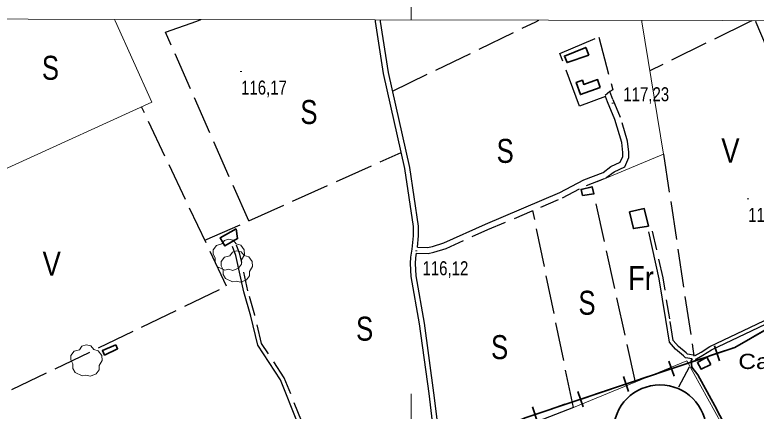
# Model space of a CAD drawing. Extents: x 483840 to 488445, y 4386047 to 4389027.
# Drawn here: x 484752.4 to 485215.3, y 4388514.2 to 4388761.9 of the extents above; entities that cross this region are included whole.
import ezdxf
from ezdxf.enums import TextEntityAlignment as Align

# ---------------------------------------------------------------- set-up
doc = ezdxf.new("R2010")
doc.units = 0
doc.header["$LTSCALE"] = 4
doc.linetypes.add('LONG_DASHED', pattern=[7.5, 6, -1.5])
doc.linetypes.add('MEDIUM_DASHED', pattern=[4.5, 3, -1.5])
for name, color, linetype, lineweight in [('1', 7, 'Continuous', 13), ('25', 7, 'LONG_DASHED', 25), ('29', 7, 'Continuous', 13), ('34', 7, 'Continuous', 35), ('38', 7, 'Continuous', 25), ('47', 7, 'Continuous', 35), ('51', 7, 'Continuous', 13), ('6', 7, 'Continuous', 35), ('7', 7, 'Continuous', 13)]:
    doc.layers.add(name, color=color, linetype=linetype, lineweight=lineweight)
doc.layers.add('31', color=7, linetype='Continuous')
doc.layers.add('5', color=7, linetype='Continuous')

msp = doc.modelspace()

# ---------------------------------------------------------------- linework, layer by layer
at = {"layer": '1'}
for p, q in [((485000, 4388758.61), (485000, 4388830.03)), ((485000, 4388525), (485000, 4388475))]:
    msp.add_line(p, q, dxfattribs=at)
msp.add_lwpolyline([(484110.5, 4388760.3), (487685.8, 4388753.5), (487681.9, 4386441.2), (484105.5, 4386448.1)], close=True, dxfattribs=at)
at = {"layer": '25'}
for p, q in [((484866.02, 4388757.98), (484868.47, 4388758.86)), ((484988.3, 4388714.2), (485077.74, 4388757.57)), ((485077.74, 4388757.57), (485079.57, 4388758.46)), ((485210.85, 4388757.32), (485149, 4388726.92)), ((485212.66, 4388758.2), (485210.85, 4388757.31)), ((485214.84, 4388758.2), (485215.21, 4388757.31)), ((485157.51, 4388674.83), (485176.51, 4388548.51)), ((485139.96, 4388532.34), (485113.97, 4388649.93)), ((485101.21, 4388516.39), (485075.87, 4388639.56)), ((485101.21, 4388516.39), (485020.66, 4388485.07))]:
    msp.add_line(p, q, dxfattribs=at)
for points in [[(484898.44, 4388633.15), (484846.53, 4388750.99), (484866.02, 4388757.98)], [(485215.21, 4388757.31), (485234.26, 4388712.09), (485248.14, 4388586.71)], [(485121.21, 4388710.73), (485105.1, 4388704.83), (485092.82, 4388737.67), (485117.03, 4388747.98), (485125.86, 4388714.91), (485123.99, 4388713.95), (485120.96, 4388711.39)], [(484723.49, 4388514.66), (484884.67, 4388592.25), (484831.6, 4388704.3)], [(484871.02, 4388621.09), (484898.5, 4388633.03), (484993.75, 4388675.81)]]:
    msp.add_lwpolyline(points, dxfattribs=at)
at = {"layer": '29'}
for points in [[(484883.46, 4388602.26), (484878.92, 4388604.38), (484877.51, 4388606.92), (484877.61, 4388609.9), (484876.24, 4388612.31), (484876.28, 4388615.06), (484878.44, 4388617.66), (484881.63, 4388618.66), (484883.28, 4388620.85), (484885.85, 4388621.68), (484888.71, 4388621.03), (484890.66, 4388618.76), (484893.47, 4388617.94), (484895.6, 4388615.09), (484895.84, 4388611.96), (484893.96, 4388608.81), (484893.96, 4388606.13), (484892.14, 4388603.52), (484888.52, 4388602.18), (484885.75, 4388602.81)], [(484888.43, 4388594.92), (484883.89, 4388597.04), (484882.48, 4388599.58), (484882.58, 4388602.56), (484881.21, 4388604.97), (484881.25, 4388607.72), (484883.41, 4388610.32), (484886.6, 4388611.32), (484888.25, 4388613.51), (484890.82, 4388614.34), (484893.68, 4388613.69), (484895.63, 4388611.42), (484898.44, 4388610.6), (484900.57, 4388607.75), (484900.81, 4388604.62), (484898.93, 4388601.47), (484898.93, 4388598.79), (484897.11, 4388596.18), (484893.49, 4388594.84), (484890.72, 4388595.47)], [(484794.53, 4388536.18), (484789.99, 4388538.3), (484788.58, 4388540.84), (484788.68, 4388543.82), (484787.31, 4388546.23), (484787.35, 4388548.98), (484789.51, 4388551.58), (484792.7, 4388552.58), (484794.35, 4388554.77), (484796.92, 4388555.6), (484799.78, 4388554.95), (484801.73, 4388552.68), (484804.54, 4388551.86), (484806.67, 4388549.01), (484806.91, 4388545.88), (484805.03, 4388542.73), (484805.03, 4388540.05), (484803.21, 4388537.44), (484799.59, 4388536.1), (484796.82, 4388536.73)]]:
    msp.add_lwpolyline(points, close=True, dxfattribs=at)
at = {"layer": '34'}
for p, q in [((485213.53, 4388560.61), (485222.2, 4388565.59)), ((485186.17, 4388548.68), (485195.65, 4388551.87)), ((485189.32, 4388555.02), (485192.5, 4388545.54)), ((485171.96, 4388543.91), (485181.44, 4388547.09)), ((485157.74, 4388539.13), (485167.22, 4388542.32)), ((485160.89, 4388545.47), (485164.07, 4388535.99)), ((485143.53, 4388534.36), (485153.01, 4388537.55)), ((485129.31, 4388529.59), (485138.79, 4388532.77)), ((485132.46, 4388535.92), (485135.64, 4388526.44)), ((485115.1, 4388524.81), (485124.58, 4388528)), ((485100.88, 4388520.04), (485110.36, 4388523.22)), ((485104.03, 4388526.37), (485107.21, 4388516.89)), ((485086.67, 4388515.26), (485096.15, 4388518.45)), ((485075.6, 4388516.82), (485078.79, 4388507.34))]:
    msp.add_line(p, q, dxfattribs=at)
for points in [[(484742, 4388368), (485071, 4388510), (485202, 4388554), (485338, 4388632), (485442, 4388724), (485439, 4388753), (485444.8, 4388757.76)], [(485200.39, 4388553.46), (485202, 4388554), (485209.2, 4388558.13)]]:
    msp.add_lwpolyline(points, dxfattribs=at)
at = {"layer": '38'}
for p, q in [((484977.67, 4388757.77), (484977.54, 4388758.65)), ((484980.82, 4388757.76), (484980.69, 4388758.64))]:
    msp.add_line(p, q, dxfattribs=at)
for points in [[(485015.38, 4388489.87), (485011.07, 4388525.18), (485005.15, 4388568.67), (485000, 4388598.29), (484999.53, 4388606.46), (484999.68, 4388610.36), (485000.57, 4388615.38), (485001.38, 4388623.79), (485001.37, 4388629.5), (484995.99, 4388665.8), (484982.61, 4388725.27), (484977.67, 4388757.77)], [(485003.81, 4388616.64), (485004.49, 4388623.64), (485004.48, 4388629.73), (484999.05, 4388666.37), (484985.67, 4388725.84), (484980.82, 4388757.76)], [(485177.32, 4388548.97), (485180.97, 4388551.04), (485186.43, 4388554.5), (485220.16, 4388570.53), (485259.22, 4388593.11), (485283.5, 4388609.42), (485318.8, 4388629.88), (485358.29, 4388660.64), (485386.3, 4388683.42), (485423.85, 4388710.78), (485435.76, 4388721.99), (485438.46, 4388724.47), (485441.33, 4388727.59)], [(485177.05, 4388545.26), (485178.07, 4388546.88), (485182.09, 4388549.16), (485187.49, 4388552.58), (485221.18, 4388568.6), (485260.38, 4388591.25), (485284.66, 4388607.57), (485320.02, 4388628.07), (485359.66, 4388658.93), (485387.64, 4388681.69), (485425.25, 4388709.1), (485437.25, 4388720.39), (485439.94, 4388722.85), (485442.73, 4388725.7)], [(485003.81, 4388616.64), (485010.2, 4388616.38), (485013.13, 4388617.06), (485020.33, 4388619.4), (485046.26, 4388631.07), (485092.81, 4388650.8), (485107.8, 4388658.7), (485119.72, 4388663.37), (485124.67, 4388666.98), (485130.51, 4388669.69), (485132.01, 4388673.37), (485132, 4388675.92), (485131.39, 4388682.14), (485127.1, 4388696.46), (485122.43, 4388707.48), (485121.2, 4388710.73)], [(485175.43, 4388546.79), (485171.3, 4388547.56), (485169.95, 4388548.76), (485165.06, 4388552.87), (485161.23, 4388557.22), (485158.88, 4388571.54), (485154.79, 4388596.97), (485148.21, 4388626.21)], [(484951.52, 4388457.57), (484949.39, 4388465.73), (484940.36, 4388482.97), (484928.92, 4388507.18), (484918.37, 4388533.79), (484904.08, 4388555.37), (484899.78, 4388573.59), (484895.33, 4388588.74), (484890.42, 4388611.54), (484888.38, 4388617.01)], [(485037.47, 4388447.58), (485024.35, 4388478.07), (485020.87, 4388484.49), (485018.37, 4388491.05), (485014.15, 4388525.57), (485008.22, 4388569.14), (485003.09, 4388598.65), (485002.64, 4388606.49), (485002.78, 4388610.02), (485003.29, 4388612.91)]]:
    msp.add_lwpolyline(points, dxfattribs=at)
at = {"layer": '38', "linetype": 'MEDIUM_DASHED'}
for points in [[(485003.29, 4388612.91), (485010.55, 4388612.62), (485014.13, 4388613.45), (485021.68, 4388615.9), (485047.76, 4388627.64), (485094.42, 4388647.42), (485109.36, 4388655.29), (485121.53, 4388660.06), (485126.58, 4388663.74), (485133.42, 4388666.91), (485135.76, 4388672.64), (485135.74, 4388676.11), (485135.08, 4388682.87), (485130.63, 4388697.73), (485125.9, 4388708.87), (485123.98, 4388713.94)], [(485177.32, 4388548.97), (485172.43, 4388549.87), (485171.57, 4388550.64), (485166.8, 4388554.65), (485163.56, 4388558.32), (485161.33, 4388571.94), (485157.23, 4388597.44), (485150.63, 4388626.76)], [(484953.97, 4388458.58), (484951.85, 4388466.67), (484942.7, 4388484.14), (484931.32, 4388508.22), (484920.7, 4388535.01), (484906.52, 4388556.43), (484902.31, 4388574.26), (484897.87, 4388589.38), (484892.94, 4388612.28), (484890.83, 4388617.92)]]:
    msp.add_lwpolyline(points, dxfattribs=at)
at = {"layer": '47'}
for points in [[(485110.9, 4388736.57), (485108.87, 4388741.52), (485095.64, 4388736.09), (485097.29, 4388732.04)], [(485117.99, 4388716.48), (485116.33, 4388721.35), (485107.68, 4388718.4), (485106.81, 4388720.93), (485103.04, 4388719.64), (485105.63, 4388712.03)], [(485113.97, 4388649.93), (485112.84, 4388654.43), (485106, 4388652.74), (485106.92, 4388649)], [(485148.06, 4388629.74), (485145.49, 4388640.76), (485136.27, 4388638.64), (485138.65, 4388628.27)], [(484890.61, 4388628.19), (484880.72, 4388622.55), (484883.6, 4388617.49), (484891.48, 4388621.98)], [(484815.42, 4388555.68), (484816.62, 4388553.13), (484808.42, 4388549.27), (484807.11, 4388552.03)], [(485187.13, 4388543.38), (485184.5, 4388547.95), (485178.6, 4388544.56), (485180.96, 4388540.44)]]:
    msp.add_lwpolyline(points, close=True, dxfattribs=at)
at = {"layer": '51'}
for p, q in [((484815.1, 4388758.08), (484814.7, 4388758.96)), ((485143.99, 4388757.44), (485143.84, 4388758.33))]:
    msp.add_line(p, q, dxfattribs=at)
for points in [[(484662.5, 4388627.22), (484838.05, 4388707.24), (484815.1, 4388758.08)], [(485116.06, 4388657.44), (485157.51, 4388674.83), (485143.99, 4388757.45)], [(485202.67, 4388490.22), (485172.05, 4388545.53), (485101.21, 4388516.39)]]:
    msp.add_lwpolyline(points, dxfattribs=at)
at = {"layer": '6', "lineweight": 25}
msp.add_line((485167.04, 4388529.47), (485173.78, 4388541.83), dxfattribs=at)
at = {"layer": '6'}
msp.add_lwpolyline([(485224.04, 4388447.11), (485207.78, 4388482.2), (485189.48, 4388517.58), (485178.95, 4388536.92), (485175.21, 4388541.77), (485174.76, 4388545.72), (485175.43, 4388546.79)], dxfattribs=at)
msp.add_circle((485155.26, 4388501.45), 29.1, dxfattribs=at)
at = {"layer": '7'}
for p, q in [((484893.18, 4388726.39), (484894.18, 4388726.39)), ((485125.15, 4388706.66), (485126.15, 4388706.66)), ((485209.79, 4388646.79), (485210.79, 4388646.79)), ((485002.58, 4388614.27), (485003.58, 4388614.27))]:
    msp.add_line(p, q, dxfattribs=at)

# ---------------------------------------------------------------- texts
at = {"layer": '31'}
for s, width, p in [('S', 0.8, (484774.65, 4388721.25)), ('S', 0.8, (484936.07, 4388693.6)), ('S', 0.8, (485058.61, 4388669.34)), ('V', 0.85, (485199.28, 4388669.57)), ('V', 0.85, (484775.45, 4388598.77)), ('Fr', 0.85, (485143.39, 4388589.8)), ('S', 0.8, (485109.7, 4388574.43)), ('S', 0.8, (484970.84, 4388558.21)), ('S', 0.8, (485055.14, 4388546.68))]:
    msp.add_text(s, height=15, dxfattribs=dict(at, width=width)).set_placement(p, align=Align.CENTER)
at = {"layer": '5', "width": 1.2}
msp.add_text('Caseta de na Nofreta', height=9.5, dxfattribs=at).set_placement((485349.13, 4388540.53), align=Align.RIGHT)
at = {"layer": '7', "width": 0.8}
for s, p in [('116,17', (484893.68, 4388712.02)), ('117,23', (485132.39, 4388707.86)), ('116,90', (485210.29, 4388632.42)), ('116,12', (485006.97, 4388599.12))]:
    msp.add_text(s, height=8.75, dxfattribs=at).set_placement(p)

doc.saveas('drawing.dxf')
